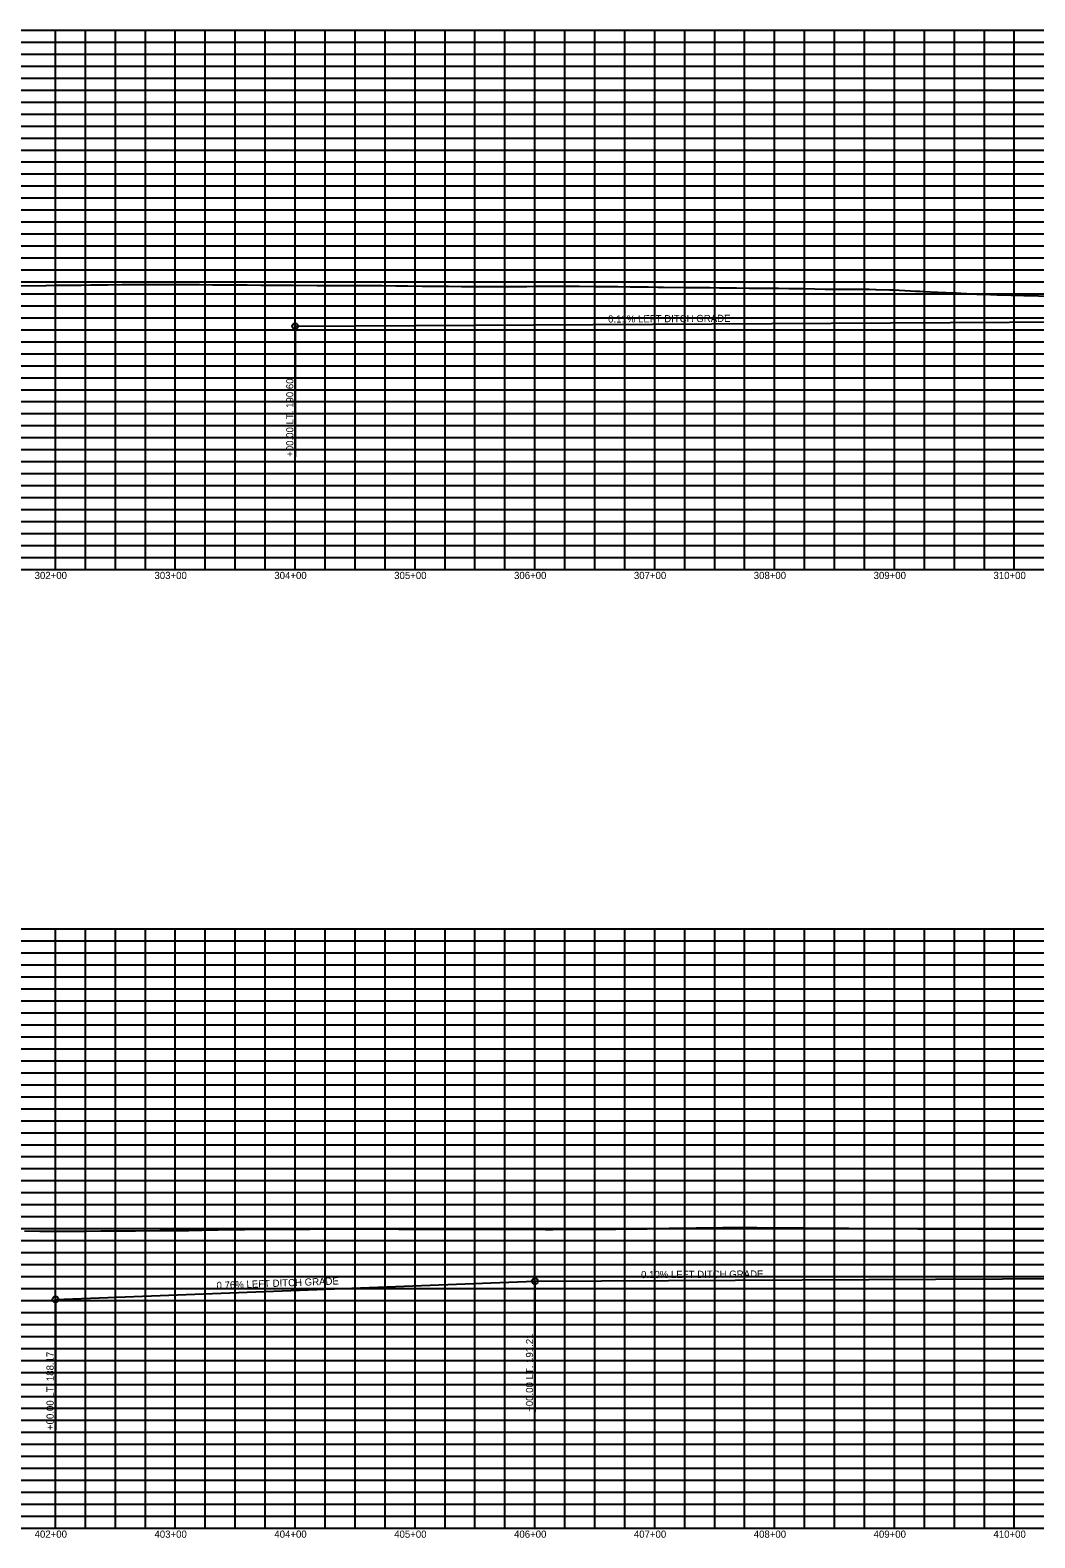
# Model space of a CAD drawing. Extents: x 1399671 to 1408349, y 1930471 to 1933387.
# Drawn here: x 1400503 to 1401341, y 1930471 to 1931729 of the extents above; entities that cross this region are included whole.
import ezdxf

# ---------------------------------------------------------------- set-up
doc = ezdxf.new("R2010")
doc.units = 0
for name, color, linetype in [('R_Exist Surface', 7, 'Continuous'), ('R_Grid', 7, 'Continuous'), ('R_Grid Annot', 7, 'Continuous'), ('R_Vert Alg', 7, 'Continuous'), ('R_Vert Alg Annot', 7, 'Continuous')]:
    doc.layers.add(name, color=color, linetype=linetype)

msp = doc.modelspace()

# ---------------------------------------------------------------- linework, layer by layer
at = {"layer": 'R_Exist Surface'}
for points in [[(1400492.3, 1931515.3), (1400516.2, 1931515.6), (1400516.3, 1931515.6), (1400516.4, 1931515.6), (1400524.2, 1931515.7), (1400533.6, 1931515.8), (1400540.5, 1931515.9), (1400540.6, 1931515.9), (1400542.7, 1931515.9), (1400546, 1931515.9), (1400553.6, 1931516), (1400553.8, 1931516), (1400566.6, 1931516.1), (1400567, 1931516.1), (1400567.9, 1931516.1), (1400579.6, 1931516.3), (1400580.2, 1931516.3), (1400589.7, 1931516.3), (1400592.6, 1931516.4), (1400593.4, 1931516.4), (1400605.2, 1931516.4), (1400606.1, 1931516.4), (1400611.6, 1931516.4), (1400617.8, 1931516.3), (1400618.9, 1931516.3), (1400630.5, 1931516.3), (1400631.6, 1931516.3), (1400633.5, 1931516.3), (1400643.1, 1931516.3), (1400644.3, 1931516.3), (1400655.3, 1931516.2), (1400655.9, 1931516.2), (1400658.4, 1931516.2), (1400669.9, 1931516.1), (1400677.2, 1931516.1), (1400681.3, 1931516), (1400684.2, 1931516), (1400695.5, 1931515.9), (1400697.1, 1931515.9), (1400699, 1931515.9), (1400718.3, 1931515.7), (1400720.3, 1931515.7), (1400720.9, 1931515.7), (1400722.4, 1931515.7), (1400742.6, 1931515.6), (1400742.7, 1931515.6), (1400745.1, 1931515.5), (1400755.3, 1931515.5), (1400758, 1931515.5), (1400764.6, 1931515.5), (1400767.9, 1931515.5), (1400771, 1931515.5), (1400780.6, 1931515.5), (1400783.9, 1931515.5), (1400786.4, 1931515.4), (1400793.2, 1931515.4), (1400796.8, 1931515.4), (1400808.3, 1931515.3), (1400811.5, 1931515.3), (1400818.3, 1931515.2), (1400830.1, 1931515.1), (1400832.1, 1931515.1), (1400839.8, 1931515), (1400849.1, 1931515), (1400852, 1931514.9), (1400863.1, 1931514.8), (1400873.6, 1931514.7), (1400873.8, 1931514.7), (1400886.4, 1931514.6), (1400895.7, 1931514.7), (1400898.9, 1931514.7), (1400910.8, 1931514.8), (1400917.5, 1931514.8), (1400924.8, 1931514.9), (1400935.2, 1931515), (1400939.4, 1931514.9), (1400949.8, 1931514.9), (1400957.8, 1931514.9), (1400961.2, 1931514.9), (1400974.2, 1931514.8), (1400980.5, 1931514.8), (1400983.1, 1931514.7), (1400990.4, 1931514.6), (1400993.3, 1931514.6), (1401003.7, 1931514.5), (1401005, 1931514.4), (1401006, 1931514.4), (1401017.1, 1931514.3), (1401018.8, 1931514.3), (1401026.8, 1931514.2), (1401030.4, 1931514.1), (1401031.5, 1931514.1), (1401048.7, 1931514), (1401053.9, 1931514), (1401054.7, 1931514), (1401054.8, 1931514), (1401055.1, 1931514), (1401070.5, 1931513.8), (1401078.2, 1931513.7), (1401083.6, 1931513.6), (1401092.4, 1931513.5), (1401102.9, 1931513.4), (1401113.4, 1931513.4), (1401114.2, 1931513.4), (1401127.5, 1931513.3), (1401136.1, 1931513.1), (1401140.9, 1931513), (1401149.2, 1931512.9), (1401157.9, 1931512.8), (1401166.3, 1931512.6), (1401171, 1931512.6), (1401179.8, 1931512.6), (1401182.1, 1931512.5), (1401184.9, 1931512.5), (1401196.2, 1931512.5), (1401201.6, 1931512.5), (1401203.1, 1931512.5), (1401208.4, 1931512.3), (1401209, 1931512.3), (1401220.2, 1931511.9), (1401222.3, 1931511.8), (1401223.5, 1931511.8), (1401237.6, 1931511.1), (1401241.7, 1931510.9), (1401245.3, 1931510.7), (1401248.4, 1931510.6), (1401260.4, 1931510), (1401267.2, 1931509.7), (1401270.9, 1931509.5), (1401275.7, 1931509.3), (1401279.5, 1931509.1), (1401289, 1931508.6), (1401292.9, 1931508.4), (1401293.9, 1931508.4), (1401298.4, 1931508.2), (1401309.9, 1931507.7), (1401310.6, 1931507.7), (1401310.9, 1931507.7), (1401332.1, 1931507.1), (1401332.7, 1931507.1), (1401334, 1931507.1), (1401354.6, 1931506.6)], [(1400498.3, 1930726.6), (1400511.1, 1930726.5), (1400511.2, 1930726.5), (1400523.8, 1930726.5), (1400524.2, 1930726.5), (1400524.2, 1930726.5), (1400536.6, 1930726.5), (1400537.1, 1930726.5), (1400546.4, 1930726.5), (1400549.1, 1930726.5), (1400550, 1930726.5), (1400562.1, 1930726.6), (1400568.7, 1930726.7), (1400574, 1930726.7), (1400575.1, 1930726.7), (1400587, 1930726.8), (1400588.4, 1930726.8), (1400591, 1930726.8), (1400611.2, 1930726.9), (1400613.2, 1930727), (1400633.6, 1930727.1), (1400635.4, 1930727.1), (1400635.5, 1930727.1), (1400657.8, 1930727.5), (1400657.8, 1930727.5), (1400660, 1930727.5), (1400680, 1930727.9), (1400681.8, 1930727.9), (1400684.6, 1930728), (1400687.5, 1930728), (1400702.3, 1930728.1), (1400709.4, 1930728.1), (1400712.8, 1930728.1), (1400724.5, 1930728.2), (1400734.2, 1930728.2), (1400736.4, 1930728.2), (1400746.8, 1930728.3), (1400747.6, 1930728.3), (1400758.4, 1930728.3), (1400760.9, 1930728.3), (1400769.1, 1930728.3), (1400771.6, 1930728.3), (1400774.3, 1930728.3), (1400784.7, 1930728.4), (1400787.7, 1930728.4), (1400791.3, 1930728.3), (1400797.7, 1930728.3), (1400801.1, 1930728.3), (1400810.8, 1930728.2), (1400813.6, 1930728.2), (1400814.4, 1930728.2), (1400823.8, 1930728.1), (1400827.8, 1930728.1), (1400835.8, 1930728), (1400836.9, 1930728), (1400841.3, 1930728), (1400856.9, 1930728), (1400858.1, 1930728), (1400865.1, 1930728), (1400879.7, 1930728.1), (1400880.4, 1930728.1), (1400888.9, 1930728), (1400896, 1930728), (1400902.6, 1930728), (1400907.2, 1930728), (1400914, 1930728), (1400920.4, 1930728), (1400924.9, 1930728), (1400933.1, 1930727.9), (1400939.1, 1930727.9), (1400946.4, 1930728), (1400947.1, 1930728), (1400952.2, 1930728), (1400960, 1930728.1), (1400965.3, 1930728.1), (1400969.4, 1930728.1), (1400973.6, 1930728.1), (1400978.4, 1930728.2), (1400987.1, 1930728.2), (1400991.5, 1930728.2), (1400991.7, 1930728.2), (1400995.6, 1930728.3), (1401004.7, 1930728.4), (1401008.4, 1930728.4), (1401014, 1930728.5), (1401017.9, 1930728.5), (1401021.3, 1930728.6), (1401031.1, 1930728.7), (1401034.2, 1930728.7), (1401036.3, 1930728.8), (1401044.3, 1930728.9), (1401047.1, 1930728.9), (1401057, 1930729), (1401058.7, 1930729.1), (1401059.4, 1930729.1), (1401069.6, 1930729.2), (1401071.7, 1930729.3), (1401081, 1930729.4), (1401082.2, 1930729.4), (1401084, 1930729.4), (1401094.8, 1930729.6), (1401096.4, 1930729.6), (1401103.3, 1930729.5), (1401108.1, 1930729.5), (1401109.4, 1930729.4), (1401121.4, 1930729.3), (1401122.4, 1930729.3), (1401125.6, 1930729.3), (1401134.6, 1930729.2), (1401147.3, 1930729.1), (1401147.9, 1930729.1), (1401147.9, 1930729.1), (1401160.3, 1930729), (1401160.6, 1930729), (1401161, 1930729), (1401170.2, 1930728.9), (1401173.4, 1930728.9), (1401173.6, 1930728.9), (1401186.1, 1930728.8), (1401186.2, 1930728.8), (1401192.5, 1930728.7), (1401198.6, 1930728.7), (1401198.9, 1930728.7), (1401198.9, 1930728.7), (1401214.8, 1930728.6), (1401221.3, 1930728.6), (1401221.9, 1930728.6), (1401237.1, 1930728.6), (1401243.7, 1930728.5), (1401244.3, 1930728.5), (1401256.9, 1930728.5), (1401257.6, 1930728.5), (1401259.4, 1930728.5), (1401270.1, 1930728.5), (1401270.8, 1930728.5), (1401281.7, 1930728.5), (1401283.2, 1930728.5), (1401295.6, 1930728.4), (1401296.4, 1930728.4), (1401304, 1930728.4), (1401308.7, 1930728.4), (1401309.5, 1930728.4), (1401321.7, 1930728.3), (1401322.6, 1930728.3), (1401334.8, 1930728.3), (1401335.7, 1930728.3), (1401347.9, 1930728.2)]]:
    msp.add_lwpolyline(points, dxfattribs=at)
at = {"layer": 'R_Grid'}
for p, q in [((1400324.2, 1931728.6), (1408324.2, 1931728.6)), ((1400324.2, 1931728.6), (1408324.2, 1931728.6)), ((1400524.2, 1931278.6), (1400524.2, 1931728.6)), ((1400549.2, 1931278.6), (1400549.2, 1931728.6)), ((1400574.2, 1931278.6), (1400574.2, 1931728.6)), ((1400599.2, 1931278.6), (1400599.2, 1931728.6)), ((1400624.2, 1931278.6), (1400624.2, 1931728.6)), ((1400649.2, 1931278.6), (1400649.2, 1931728.6)), ((1400674.2, 1931278.6), (1400674.2, 1931728.6)), ((1400699.2, 1931278.6), (1400699.2, 1931728.6)), ((1400724.2, 1931278.6), (1400724.2, 1931728.6)), ((1400749.2, 1931278.6), (1400749.2, 1931728.6)), ((1400774.2, 1931278.6), (1400774.2, 1931728.6)), ((1400799.2, 1931278.6), (1400799.2, 1931728.6)), ((1400824.2, 1931278.6), (1400824.2, 1931728.6)), ((1400849.2, 1931278.6), (1400849.2, 1931728.6)), ((1400874.2, 1931278.6), (1400874.2, 1931728.6)), ((1400899.2, 1931278.6), (1400899.2, 1931728.6)), ((1400924.2, 1931278.6), (1400924.2, 1931728.6)), ((1400949.2, 1931278.6), (1400949.2, 1931728.6)), ((1400974.2, 1931278.6), (1400974.2, 1931728.6)), ((1400999.2, 1931278.6), (1400999.2, 1931728.6)), ((1401024.2, 1931278.6), (1401024.2, 1931728.6)), ((1401049.2, 1931278.6), (1401049.2, 1931728.6)), ((1401074.2, 1931278.6), (1401074.2, 1931728.6)), ((1401099.2, 1931278.6), (1401099.2, 1931728.6)), ((1401124.2, 1931278.6), (1401124.2, 1931728.6)), ((1401149.2, 1931278.6), (1401149.2, 1931728.6)), ((1401174.2, 1931278.6), (1401174.2, 1931728.6)), ((1401199.2, 1931278.6), (1401199.2, 1931728.6)), ((1401224.2, 1931278.6), (1401224.2, 1931728.6)), ((1401249.2, 1931278.6), (1401249.2, 1931728.6)), ((1401274.2, 1931278.6), (1401274.2, 1931728.6)), ((1401299.2, 1931278.6), (1401299.2, 1931728.6)), ((1401324.2, 1931278.6), (1401324.2, 1931728.6)), ((1400324.2, 1931718.6), (1408324.2, 1931718.6)), ((1400324.2, 1931708.6), (1408324.2, 1931708.6)), ((1400324.2, 1931698.6), (1408324.2, 1931698.6)), ((1400324.2, 1931688.6), (1408324.2, 1931688.6)), ((1400324.2, 1931678.6), (1408324.2, 1931678.6)), ((1400324.2, 1931668.6), (1408324.2, 1931668.6)), ((1400324.2, 1931658.6), (1408324.2, 1931658.6)), ((1400324.2, 1931648.6), (1408324.2, 1931648.6)), ((1400324.2, 1931638.6), (1408324.2, 1931638.6)), ((1400324.2, 1931628.6), (1408324.2, 1931628.6)), ((1400324.2, 1931618.6), (1408324.2, 1931618.6)), ((1400324.2, 1931608.6), (1408324.2, 1931608.6)), ((1400324.2, 1931598.6), (1408324.2, 1931598.6)), ((1400324.2, 1931588.6), (1408324.2, 1931588.6)), ((1400324.2, 1931578.6), (1408324.2, 1931578.6)), ((1400324.2, 1931568.6), (1408324.2, 1931568.6)), ((1400324.2, 1931558.6), (1408324.2, 1931558.6)), ((1400324.2, 1931548.6), (1408324.2, 1931548.6)), ((1400324.2, 1931538.6), (1408324.2, 1931538.6)), ((1400324.2, 1931528.6), (1408324.2, 1931528.6)), ((1400324.2, 1931518.6), (1408324.2, 1931518.6)), ((1400324.2, 1931508.6), (1408324.2, 1931508.6)), ((1400324.2, 1931498.6), (1408324.2, 1931498.6)), ((1400324.2, 1931488.6), (1408324.2, 1931488.6)), ((1400324.2, 1931478.6), (1408324.2, 1931478.6)), ((1400324.2, 1931468.6), (1408324.2, 1931468.6)), ((1400324.2, 1931458.6), (1408324.2, 1931458.6)), ((1400324.2, 1931448.6), (1408324.2, 1931448.6)), ((1400324.2, 1931438.6), (1408324.2, 1931438.6)), ((1400324.2, 1931428.6), (1408324.2, 1931428.6)), ((1400324.2, 1931418.6), (1408324.2, 1931418.6)), ((1400324.2, 1931408.6), (1408324.2, 1931408.6)), ((1400324.2, 1931398.6), (1408324.2, 1931398.6)), ((1400324.2, 1931388.6), (1408324.2, 1931388.6)), ((1400324.2, 1931378.6), (1408324.2, 1931378.6)), ((1400324.2, 1931368.6), (1408324.2, 1931368.6)), ((1400324.2, 1931358.6), (1408324.2, 1931358.6)), ((1400324.2, 1931348.6), (1408324.2, 1931348.6)), ((1400324.2, 1931338.6), (1408324.2, 1931338.6)), ((1400324.2, 1931328.6), (1408324.2, 1931328.6)), ((1400324.2, 1931318.6), (1408324.2, 1931318.6)), ((1400324.2, 1931308.6), (1408324.2, 1931308.6)), ((1400324.2, 1931298.6), (1408324.2, 1931298.6)), ((1400324.2, 1931288.6), (1408324.2, 1931288.6)), ((1400324.2, 1931278.6), (1408324.2, 1931278.6)), ((1400324.2, 1930978.6), (1407124.2, 1930978.6)), ((1400324.2, 1930978.6), (1407124.2, 1930978.6)), ((1400524.2, 1930478.6), (1400524.2, 1930978.6)), ((1400549.2, 1930478.6), (1400549.2, 1930978.6)), ((1400574.2, 1930478.6), (1400574.2, 1930978.6)), ((1400599.2, 1930478.6), (1400599.2, 1930978.6)), ((1400624.2, 1930478.6), (1400624.2, 1930978.6)), ((1400649.2, 1930478.6), (1400649.2, 1930978.6)), ((1400674.2, 1930478.6), (1400674.2, 1930978.6)), ((1400699.2, 1930478.6), (1400699.2, 1930978.6)), ((1400724.2, 1930478.6), (1400724.2, 1930978.6)), ((1400749.2, 1930478.6), (1400749.2, 1930978.6)), ((1400774.2, 1930478.6), (1400774.2, 1930978.6)), ((1400799.2, 1930478.6), (1400799.2, 1930978.6)), ((1400824.2, 1930478.6), (1400824.2, 1930978.6)), ((1400849.2, 1930478.6), (1400849.2, 1930978.6)), ((1400874.2, 1930478.6), (1400874.2, 1930978.6)), ((1400899.2, 1930478.6), (1400899.2, 1930978.6)), ((1400924.2, 1930478.6), (1400924.2, 1930978.6)), ((1400949.2, 1930478.6), (1400949.2, 1930978.6)), ((1400974.2, 1930478.6), (1400974.2, 1930978.6)), ((1400999.2, 1930478.6), (1400999.2, 1930978.6)), ((1401024.2, 1930478.6), (1401024.2, 1930978.6)), ((1401049.2, 1930478.6), (1401049.2, 1930978.6)), ((1401074.2, 1930478.6), (1401074.2, 1930978.6)), ((1401099.2, 1930478.6), (1401099.2, 1930978.6)), ((1401124.2, 1930478.6), (1401124.2, 1930978.6)), ((1401149.2, 1930478.6), (1401149.2, 1930978.6)), ((1401174.2, 1930478.6), (1401174.2, 1930978.6)), ((1401199.2, 1930478.6), (1401199.2, 1930978.6)), ((1401224.2, 1930478.6), (1401224.2, 1930978.6)), ((1401249.2, 1930478.6), (1401249.2, 1930978.6)), ((1401274.2, 1930478.6), (1401274.2, 1930978.6)), ((1401299.2, 1930478.6), (1401299.2, 1930978.6)), ((1401324.2, 1930478.6), (1401324.2, 1930978.6)), ((1400324.2, 1930968.6), (1407124.2, 1930968.6)), ((1400324.2, 1930958.6), (1407124.2, 1930958.6)), ((1400324.2, 1930948.6), (1407124.2, 1930948.6)), ((1400324.2, 1930938.6), (1407124.2, 1930938.6)), ((1400324.2, 1930928.6), (1407124.2, 1930928.6)), ((1400324.2, 1930918.6), (1407124.2, 1930918.6)), ((1400324.2, 1930908.6), (1407124.2, 1930908.6)), ((1400324.2, 1930898.6), (1407124.2, 1930898.6)), ((1400324.2, 1930888.6), (1407124.2, 1930888.6)), ((1400324.2, 1930878.6), (1407124.2, 1930878.6)), ((1400324.2, 1930868.6), (1407124.2, 1930868.6)), ((1400324.2, 1930858.6), (1407124.2, 1930858.6)), ((1400324.2, 1930848.6), (1407124.2, 1930848.6)), ((1400324.2, 1930838.6), (1407124.2, 1930838.6)), ((1400324.2, 1930828.6), (1407124.2, 1930828.6)), ((1400324.2, 1930818.6), (1407124.2, 1930818.6)), ((1400324.2, 1930808.6), (1407124.2, 1930808.6)), ((1400324.2, 1930798.6), (1407124.2, 1930798.6)), ((1400324.2, 1930788.6), (1407124.2, 1930788.6)), ((1400324.2, 1930778.6), (1407124.2, 1930778.6)), ((1400324.2, 1930768.6), (1407124.2, 1930768.6)), ((1400324.2, 1930758.6), (1407124.2, 1930758.6)), ((1400324.2, 1930748.6), (1407124.2, 1930748.6)), ((1400324.2, 1930738.6), (1407124.2, 1930738.6)), ((1400324.2, 1930728.6), (1407124.2, 1930728.6)), ((1400324.2, 1930718.6), (1407124.2, 1930718.6)), ((1400324.2, 1930708.6), (1407124.2, 1930708.6)), ((1400324.2, 1930698.6), (1407124.2, 1930698.6)), ((1400324.2, 1930688.6), (1407124.2, 1930688.6)), ((1400324.2, 1930678.6), (1407124.2, 1930678.6)), ((1400324.2, 1930668.6), (1407124.2, 1930668.6)), ((1400324.2, 1930658.6), (1407124.2, 1930658.6)), ((1400324.2, 1930648.6), (1407124.2, 1930648.6)), ((1400324.2, 1930638.6), (1407124.2, 1930638.6)), ((1400324.2, 1930628.6), (1407124.2, 1930628.6)), ((1400324.2, 1930618.6), (1407124.2, 1930618.6)), ((1400324.2, 1930608.6), (1407124.2, 1930608.6)), ((1400324.2, 1930598.6), (1407124.2, 1930598.6)), ((1400324.2, 1930588.6), (1407124.2, 1930588.6)), ((1400324.2, 1930578.6), (1407124.2, 1930578.6)), ((1400324.2, 1930568.6), (1407124.2, 1930568.6)), ((1400324.2, 1930558.6), (1407124.2, 1930558.6)), ((1400324.2, 1930548.6), (1407124.2, 1930548.6)), ((1400324.2, 1930538.6), (1407124.2, 1930538.6)), ((1400324.2, 1930528.6), (1407124.2, 1930528.6)), ((1400324.2, 1930518.6), (1407124.2, 1930518.6)), ((1400324.2, 1930508.6), (1407124.2, 1930508.6)), ((1400324.2, 1930498.6), (1407124.2, 1930498.6)), ((1400324.2, 1930488.6), (1407124.2, 1930488.6)), ((1400324.2, 1930478.6), (1407124.2, 1930478.6))]:
    msp.add_line(p, q, dxfattribs=at)
at = {"layer": 'R_Vert Alg'}
for p, q in [((1400724.2, 1931481.6), (1402114.2, 1931489.3)), ((1400524.2, 1930669.5), (1400924.2, 1930684.7)), ((1400924.2, 1930684.7), (1402758.2, 1930693.8))]:
    msp.add_line(p, q, dxfattribs=at)
at = {"layer": 'R_Vert Alg Annot'}
for p, q in [((1400724.2, 1931481.6), (1400724.2, 1931456.6)), ((1400724.2, 1931456.6), (1400724.2, 1931372.6)), ((1400924.2, 1930684.7), (1400924.2, 1930659.7)), ((1400524.2, 1930669.5), (1400524.2, 1930644.5)), ((1400924.2, 1930659.7), (1400924.2, 1930575.7)), ((1400524.2, 1930644.5), (1400524.2, 1930560.5))]:
    msp.add_line(p, q, dxfattribs=at)
for centre in [(1400724.2, 1931481.6), (1400924.2, 1930684.7), (1400524.2, 1930669.5)]:
    msp.add_circle(centre, 2.5, dxfattribs=at)

# ---------------------------------------------------------------- texts
at = {"layer": 'R_Grid Annot'}
for s, p in [('302+00', (1400506.8, 1931270.6)), ('303+00', (1400606.8, 1931270.6)), ('304+00', (1400706.8, 1931270.6)), ('305+00', (1400806.8, 1931270.6)), ('306+00', (1400906.8, 1931270.6)), ('307+00', (1401006.8, 1931270.6)), ('308+00', (1401106.8, 1931270.6)), ('309+00', (1401206.8, 1931270.6)), ('310+00', (1401306.8, 1931270.6)), ('402+00', (1400506.8, 1930470.6)), ('403+00', (1400606.8, 1930470.6)), ('404+00', (1400706.8, 1930470.6)), ('405+00', (1400806.8, 1930470.6)), ('406+00', (1400906.8, 1930470.6)), ('407+00', (1401006.8, 1930470.6)), ('408+00', (1401106.8, 1930470.6)), ('409+00', (1401206.8, 1930470.6)), ('410+00', (1401306.8, 1930470.6))]:
    msp.add_text(s, height=6, dxfattribs=at).set_placement(p)
at = {"layer": 'R_Vert Alg Annot'}
for s, rotation, p in [('0.11% LEFT DITCH GRADE', 0.3153, (1400985.3, 1931484.6)), ('+00.00 LT. 190.60', 90, (1400722.7, 1931372.6)), ('0.76% LEFT DITCH GRADE', 2.1762, (1400658.7, 1930678.1)), ('0.10% LEFT DITCH GRADE', 0.2859, (1401012.8, 1930687.2)), ('+00.00 LT. 191.21', 90, (1400922.7, 1930575.7)), ('+00.00 LT. 188.17', 90, (1400522.7, 1930560.5))]:
    msp.add_text(s, height=6, rotation=rotation, dxfattribs=at).set_placement(p)

doc.saveas('drawing.dxf')
